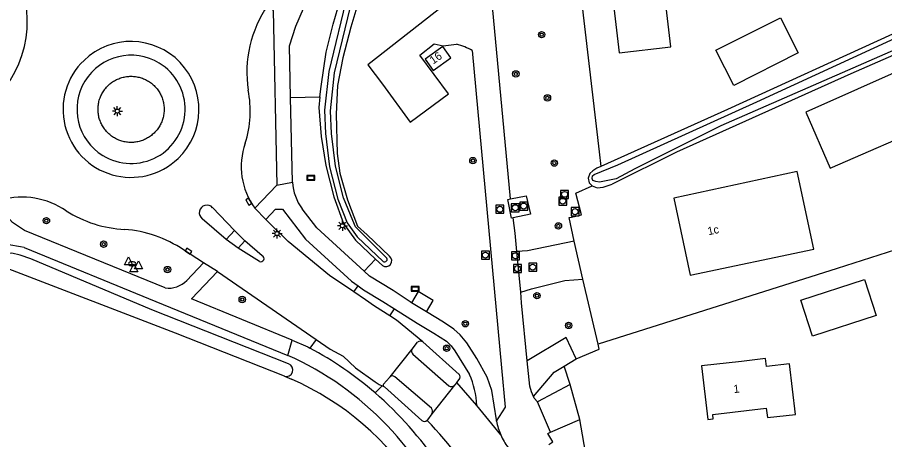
# Model space of a CAD drawing. Extents: x 140000 to 143000, y 403500 to 406000.
# Drawn here: x 140453.4 to 140561.8, y 404433.8 to 404486.5 of the extents above; entities that cross this region are included whole.
import ezdxf

# ---------------------------------------------------------------- set-up
doc = ezdxf.new("R2010")
doc.units = 0
for name, color, linetype in [('gg-afsc-hekwerk', 7, 'Continuous'), ('gg-anno-huisnummerreeks BGT', 7, 'Continuous'), ('gg-bbg-bijgebouw', 7, 'Continuous'), ('gg-bbg-gedigitaliseerde bijgebouw', 7, 'Continuous'), ('gg-bbg-hoofdgebouw', 7, 'Continuous'), ('gg-knt-verharding', 7, 'Continuous'), ('gg-knt-verharding nz', 7, 'Continuous'), ('gg-kntw-bovenkant insteek waterloop', 7, 'Continuous'), ('gg-kntw-waterlijn', 7, 'Continuous'), ('gg-kwrk-betonelement', 7, 'Continuous'), ('gt-grn-groengrens', 7, 'Continuous'), ('gt-grn-groengrens NZ', 7, 'Continuous'), ('gt-grn-vlakafsluiter', 7, 'Continuous'), ('gt-grn-weggrens', 7, 'Continuous'), ('gt-symb-boom', 7, 'Continuous'), ('gt-symb-brandkraan', 7, 'Continuous'), ('gt-symb-informatiebord', 7, 'Continuous'), ('gt-symb-kolk', 7, 'Continuous'), ('gt-symb-lichtmast', 7, 'Continuous'), ('gt-symb-reclamebord', 7, 'Continuous'), ('gt-symb-rioolschacht', 7, 'Continuous'), ('gt-symb-waterafsluiter', 7, 'Continuous')]:
    doc.layers.add(name, color=color, linetype=linetype)

# ---------------------------------------------------------------- blocks, each defined once
blk = doc.blocks.new('gt0-RS')
at = {"layer": 'gt-symb-rioolschacht'}
blk.add_lwpolyline([(-0.5, -0.5), (0.5, -0.5), (0.5, 0.5), (-0.5, 0.5)], close=True, dxfattribs=at)
blk.add_circle((0, 0), 0.375, dxfattribs=at)
blk = doc.blocks.new('gt0-BOOM')
at = {"layer": 'gt-symb-boom'}
for radius in [0.4, 0.2]:
    blk.add_circle((0, 0), radius, dxfattribs=at)
blk = doc.blocks.new('gt0-IBORD')
at = {"layer": 'gt-symb-informatiebord'}
blk.add_lwpolyline([(-0.5, 0.29), (-0.5, -0.29), (0.5, -0.29), (0.5, 0.29), (-0.5, 0.29)], dxfattribs=at)
blk.add_lwpolyline([(-0.42, -0.21), (0.42, -0.21), (0.42, 0.21), (-0.42, 0.21)], close=True, dxfattribs=at)
blk = doc.blocks.new('gt0-LMAST')
at = {"layer": 'gt-symb-lichtmast'}
for p, q in [((-0.18, 0.17), (-0.45, 0.44)), ((-0.01, 0.25), (-0.01, 0.62)), ((0.17, 0.17), (0.44, 0.44)), ((-0.26, 0), (-0.63, 0)), ((-0.18, -0.18), (-0.45, -0.45)), ((-0.01, -0.25), (-0.01, -0.63)), ((0.44, -0.45), (0.17, -0.18)), ((0.24, 0), (0.62, 0))]:
    blk.add_line(p, q, dxfattribs=at)
blk.add_circle((-0.01, 0), 0.25, dxfattribs=at)
blk = doc.blocks.new('gt0-RBORD')
at = {"layer": 'gt-symb-reclamebord'}
blk.add_lwpolyline([(-0.5, 0.29), (-0.5, -0.29), (0.5, -0.29), (0.5, 0.29), (-0.5, 0.29)], dxfattribs=at)
blk.add_lwpolyline([(-0.42, -0.21), (0.42, -0.21), (0.42, 0.21), (-0.42, 0.21)], close=True, dxfattribs=at)
blk = doc.blocks.new('gt0-KOLK')
at = {"layer": 'gt-symb-kolk'}
blk.add_lwpolyline([(0, 0), (0.38, 0), (0.38, 0.4), (-0.37, 0.4), (-0.37, 0), (0, 0)], dxfattribs=at)
blk = doc.blocks.new('gt0-WAFSL')
at = {"layer": 'gt-symb-waterafsluiter'}
for p, q in [((-0.5, -0.33), (0, 0.67)), ((0, 0.67), (0.5, -0.33)), ((0.5, -0.33), (-0.5, -0.33))]:
    blk.add_line(p, q, dxfattribs=at)
blk = doc.blocks.new('gt0-BR')
at = {"layer": 'gt-symb-brandkraan'}
for centre, radius, start, end in [((-0.24, 0), 0.206, 107.5669, 252.4331), ((0.6, -2.66), 3, 106.892, 107.5669), ((0, -0.69), 0.938, 73.108, 106.892), ((-0.6, -2.66), 3, 72.4331, 73.108), ((0.24, 0), 0.206, 287.567, 72.4331), ((0.6, 2.66), 3, 252.4331, 253.108), ((0, 0.69), 0.938, 253.108, 286.8921), ((-0.6, 2.66), 3, 286.8921, 287.567)]:
    blk.add_arc(centre, radius, start, end, dxfattribs=at)

msp = doc.modelspace()

# ---------------------------------------------------------------- linework, layer by layer
at = {"layer": 'gg-afsc-hekwerk'}
msp.add_lwpolyline([(140522.62, 404461.55), (140523.86, 404461.84), (140523.16, 404464.53), (140525.23, 404465.47)], dxfattribs=at)
at = {"layer": 'gg-bbg-bijgebouw'}
for points in [[(140528.58, 404482.06), (140535.03, 404482.81), (140533.59, 404495.22), (140527.14, 404494.47), (140528.58, 404482.06)], [(140564.83, 404480.4), (140551.92, 404474.66), (140554.95, 404467.67), (140567.98, 404473.32), (140564.83, 404480.4)], [(140560.68, 404449.24), (140552.74, 404446.68), (140551.29, 404451.18), (140559.22, 404453.75), (140560.68, 404449.24)]]:
    msp.add_lwpolyline(points, dxfattribs=at)
at = {"layer": 'gg-bbg-gedigitaliseerde bijgebouw'}
msp.add_lwpolyline([(140540.68, 404482.42), (140548.72, 404486.46), (140550.94, 404482.05), (140542.9, 404478.01), (140540.68, 404482.42)], dxfattribs=at)
at = {"layer": 'gg-bbg-hoofdgebouw'}
for points in [[(140507.57, 404481.43), (140506.57, 404482.86), (140504.33, 404481.28), (140505.33, 404479.86), (140507.57, 404481.43)], [(140550.82, 404467.25), (140535.42, 404463.91), (140537.46, 404454.28), (140552.91, 404457.56), (140550.82, 404467.25)], [(140546.99, 404442.89), (140546.87, 404443.87), (140543.85, 404443.51), (140538.88, 404442.99), (140539.66, 404436.28), (140540.33, 404436.35), (140540.27, 404436.89), (140546.97, 404437.7), (140547.11, 404436.5), (140550.63, 404436.91), (140549.88, 404443.23), (140546.99, 404442.89)]]:
    msp.add_lwpolyline(points, dxfattribs=at)
at = {"layer": 'gg-knt-verharding'}
for p, q in [((140487.75, 404465.9), (140487.53, 404476.49)), ((140485.81, 404465.55), (140483.06, 404462.66)), ((140477.79, 404462.73), (140480.53, 404459.89)), ((140484.43, 404461.26), (140483.06, 404462.66)), ((140479.49, 404458.75), (140476.48, 404461.34)), ((140479.49, 404458.75), (140480.53, 404459.89)), ((140480.53, 404459.89), (140481.81, 404458.57)), ((140480.99, 404457.69), (140479.49, 404458.75)), ((140480.99, 404457.69), (140481.81, 404458.57)), ((140483.99, 404456.72), (140481.81, 404458.57)), ((140476.66, 404455.85), (140474.13, 404457.47)), ((140483.64, 404456), (140480.99, 404457.69)), ((140476.66, 404455.85), (140474.57, 404453.64)), ((140478.39, 404454.76), (140476.66, 404455.85)), ((140478.39, 404454.76), (140490.71, 404446.27)), ((140504.5, 404449.73), (140502.65, 404450.86)), ((140502.73, 404445.04), (140503.38, 404445.93)), ((140502.82, 404444.45), (140507.31, 404440.47)), ((140521.73, 404442.95), (140523.23, 404443.83)), ((140505.12, 404437.7), (140500.54, 404441.58)), ((140508.3, 404440.9), (140508, 404440.54)), ((140510.81, 404438.03), (140508.3, 404440.9)), ((140522.45, 404440.65), (140518.39, 404438.46)), ((140498.98, 404440.47), (140499.19, 404440.38)), ((140513.8, 404434.35), (140510.81, 404438.03)), ((140520.01, 404434.7), (140523.65, 404436.26))]:
    msp.add_line(p, q, dxfattribs=at)
for points in [[(140520.96, 404513.15), (140521.2, 404511.38), (140526.1, 404469.69), (140526.29, 404467.87)], [(140487.53, 404476.49), (140487.39, 404482.93), (140488.2, 404485.4), (140489.14, 404487.62), (140490.18, 404489.76), (140497.41, 404498.62)], [(140515.01, 404463.83), (140512.75, 404487.86), (140513.62, 404490.15), (140513.59, 404491.55), (140512.68, 404492.73), (140497.19, 404480.57), (140499.03, 404478.17), (140502.45, 404473.42), (140507.27, 404476.95), (140503.69, 404481.79), (140505.47, 404483.18), (140506.59, 404482.94), (140508.27, 404483.14)], [(140484.67, 404488), (140485.35, 404487.37), (140485.81, 404465.55)], [(140513.27, 404436.07), (140514.4, 404437.81), (140513.94, 404442.74), (140510.24, 404482.36)], [(140471.84, 404452.7), (140454.28, 404459.86), (140452.8, 404460.86), (140452.12, 404461.61), (140451.39, 404463.71)], [(140484.43, 404461.26), (140485.66, 404462.56), (140486.51, 404462.55), (140489.41, 404458.81), (140495.13, 404453.55), (140495.96, 404452.95)], [(140496.72, 404454.79), (140490.81, 404460.19), (140488.97, 404462.59)], [(140495.44, 404452.2), (140492.38, 404454.24), (140487.22, 404458.49), (140484.43, 404461.26)], [(140515.81, 404457.25), (140515.6, 404459.53), (140515.32, 404461.45)], [(140575.92, 404441.74), (140571.45, 404460.14), (140555.84, 404455.11), (140525.94, 404445.69)], [(140522.95, 404458.56), (140517.14, 404457.34), (140515.81, 404457.25)], [(140454.25, 404457.76), (140470.71, 404451.02), (140487.17, 404444.27)], [(140487.71, 404446.19), (140475.16, 404451.36), (140478.39, 404454.76)], [(140502.65, 404450.86), (140502.48, 404450.97), (140500.34, 404452.38), (140497.38, 404454.18), (140496.72, 404454.79)], [(140516.28, 404452.17), (140517.61, 404452.61), (140521.79, 404453.64), (140524.06, 404453.81)], [(140495.96, 404452.95), (140496.63, 404452.47), (140499.05, 404451.01), (140500.5, 404450.1)], [(140499.92, 404449.22), (140498.03, 404450.43), (140496.9, 404451.22), (140495.44, 404452.2)], [(140517.1, 404443.58), (140516.36, 404450.85), (140516.28, 404452.17)], [(140500.5, 404450.1), (140503.36, 404448.32), (140505.44, 404447.07), (140507, 404446.05), (140507.6, 404445.49), (140508.06, 404444.84), (140509.9, 404441.9)], [(140513.27, 404436.07), (140513.24, 404436.22), (140512.66, 404439.89), (140512.1, 404441.57), (140510.81, 404443.9), (140509.53, 404445.84), (140508.72, 404446.86), (140507.92, 404447.54), (140506.62, 404448.44), (140504.5, 404449.73)], [(140504.05, 404445.95), (140500.76, 404448.68), (140499.92, 404449.22)], [(140487.71, 404446.19), (140489.67, 404445.33), (140489.94, 404445.18)], [(140490.71, 404446.27), (140492.47, 404445.06), (140494.08, 404444.18), (140495.62, 404442.74), (140498.08, 404440.99), (140498.6, 404440.64), (140498.98, 404440.47)], [(140523.23, 404443.83), (140521.97, 404446.53), (140517.1, 404443.58)], [(140517.87, 404439.14), (140520.48, 404442.18), (140521.73, 404442.95)], [(140499.15, 404440.69), (140499.89, 404441.51), (140499.96, 404441.59)], [(140518.39, 404438.46), (140517.97, 404438.95), (140517.87, 404439.14)], [(140505.17, 404436.99), (140504.62, 404436.21), (140504.58, 404436.17)], [(140519.81, 404433.16), (140520.28, 404433.47), (140519.66, 404434.54), (140520.01, 404434.7)]]:
    msp.add_lwpolyline(points, dxfattribs=at)
for centre, radius, start, end in [((140441.02, 404485.97), 13.61, 298.4785, 15.9057), ((140496.9, 404479.62), 14.83, 145.5807, 188.5723), ((140467.59, 404475), 8.49, 313.788, 133.7499), ((140506.5, 404475.84), 7.51, 60.1621, 76.3458), ((140467.59, 404475), 8.49, 133.7499, 313.788), ((140469.08, 404474.8), 13.41, 342.5234, 11.2135), ((140490.07, 404467.83), 8.71, 160.2347, 216.4345), ((140494.14, 404466.38), 6.41, 184.345, 216.2764), ((140453.95, 404454.25), 9.8, 55.5742, 105.1133), ((140467.59, 404475.16), 15.17, 237.724, 267.0571), ((140477.08, 404462.09), 0.957, 41.869, 231.7851), ((140465.68, 404444.92), 15.13, 56.0472, 85.7271), ((140450.4, 404440.5), 17.68, 77.4258, 102.5145), ((140483.81, 404456.37), 0.401, 245.3953, 63.2659), ((140472.26, 404455.91), 3.24, 262.5951, 315.4691), ((140503.73, 404445.47), 0.576, 56.5546, 127.7192), ((140468.75, 404405.6), 44.9, 49.192, 61.8333), ((140503.06, 404444.79), 0.42, 142.7754, 234.239), ((140471.33, 404408.63), 39.01, 21.2344, 66.0399), ((140500.24, 404441.3), 0.409, 42.8173, 134.0493), ((140498.71, 404437.24), 12.12, 3.748, 22.6407), ((140499.32, 404440.55), 0.22, 143.2526, 234.6549), ((140468.74, 404405.61), 44.9, 18.6655, 49.1813), ((140507.61, 404440.95), 0.57, 238.8281, 313.4677), ((140504.72, 404437.31), 0.554, 324.5656, 44.0208), ((140472.26, 404404.56), 45.2, 12.7234, 44.3624), ((140520.95, 404437.49), 7.82, 190.4271, 203.6944)]:
    msp.add_arc(centre, radius, start, end, dxfattribs=at)
at = {"layer": 'gg-knt-verharding nz'}
for p, q in [((140516.28, 404452.17), (140515.81, 404457.25)), ((140520.01, 404434.7), (140518.39, 404438.46))]:
    msp.add_line(p, q, dxfattribs=at)
msp.add_lwpolyline([(140517.87, 404439.14), (140517.61, 404439.72), (140517.43, 404440.44), (140517.1, 404443.58)], dxfattribs=at)
at = {"layer": 'gg-kntw-bovenkant insteek waterloop'}
msp.add_line((140498.14, 404456.31), (140499.01, 404455.5), dxfattribs=at)
for points in [[(140666.62, 404527.97), (140659.46, 404524.87), (140640.73, 404516.48), (140623.81, 404509.02), (140621.4, 404508.04), (140620.12, 404507.42), (140618.62, 404506.41), (140617.55, 404505.74), (140597.26, 404497.06), (140576.48, 404487.74), (140557.53, 404479.45), (140535.75, 404469.66), (140527.71, 404465.66)], [(140491.19, 404476.56), (140491.33, 404477.87), (140491.97, 404482.14), (140492.87, 404485.65), (140493.74, 404488.71), (140494.69, 404491.34), (140495.81, 404493.54), (140497.39, 404496.11), (140499.15, 404498.51), (140502.16, 404502.15), (140505.71, 404505.21), (140507.48, 404506.7), (140517.05, 404513.8)], [(140621.8, 404510.82), (140612.07, 404506.52), (140586.99, 404495.35), (140562.75, 404484.41), (140542.11, 404474.98), (140526.29, 404467.87)], [(140505.76, 404502.31), (140503.67, 404500.63), (140501.67, 404498.34), (140499.95, 404496.3), (140497.92, 404492.66), (140496.32, 404489.47), (140495.05, 404485.29), (140494.07, 404481.44), (140493.38, 404478.01), (140493.21, 404474.4), (140493.35, 404469.5), (140493.7, 404467.04), (140494.65, 404463.69), (140495.88, 404460.41), (140497.11, 404459.33), (140499.87, 404456.67)], [(140491.19, 404476.56), (140491.05, 404475.26), (140491.35, 404471.61), (140491.94, 404467.99), (140492.92, 404464.08), (140494.16, 404460.77), (140495.62, 404458.67), (140498.14, 404456.31)], [(140526.29, 404467.87), (140525.8, 404467.65), (140525.31, 404467.35), (140524.9, 404466.99), (140524.73, 404466.43), (140524.84, 404465.83), (140525.23, 404465.47)], [(140525.23, 404465.47), (140525.42, 404465.39), (140525.83, 404465.22), (140526.57, 404465.3), (140527.71, 404465.66)], [(140487.27, 404443.22), (140470.2, 404449.98), (140455.09, 404456.32), (140453.74, 404456.81), (140452.71, 404457.05), (140452.26, 404456.99), (140451.76, 404456.55), (140451.57, 404456.09), (140451.56, 404455.67), (140451.82, 404455.3)], [(140486.75, 404441.67), (140473.13, 404447.04), (140452.26, 404455.08), (140451.82, 404455.3)]]:
    msp.add_lwpolyline(points, dxfattribs=at)
for centre, radius, start, end in [((140499.44, 404456.08), 0.728, 233.5478, 53.1062), ((140487, 404442.45), 0.819, 252.4404, 70.0698)]:
    msp.add_arc(centre, radius, start, end, dxfattribs=at)
at = {"layer": 'gg-kntw-waterlijn'}
for points in [[(140517.64, 404513.01), (140510.45, 404507.83), (140502.62, 404501.65), (140498.04, 404496.02), (140494.67, 404489.59), (140492.3, 404479.73), (140491.77, 404474.9), (140491.91, 404471.98), (140492.41, 404467.84), (140493.42, 404463.79), (140494.61, 404460.85), (140495.86, 404459.09), (140499.08, 404456.01)], [(140499.47, 404456.52), (140495.65, 404460.34), (140495.31, 404461.14), (140494.15, 404463.97), (140493.15, 404467.93), (140492.66, 404472.01), (140492.52, 404474.82), (140493.03, 404479.56), (140495.33, 404489.24), (140498.62, 404495.55), (140503.15, 404501.11), (140510.89, 404507.22), (140518.09, 404512.41)], [(140577.84, 404488.98), (140557.79, 404480.15), (140541.28, 404472.97), (140530.56, 404467.57), (140528.22, 404466.34), (140526.13, 404465.91), (140525.68, 404465.98), (140525.31, 404466.11), (140525.2, 404466.39), (140525.27, 404466.69), (140525.47, 404466.87), (140528.4, 404468.09), (140545.77, 404475.93), (140567.76, 404486.05), (140593.6, 404497.59)]]:
    msp.add_lwpolyline(points, dxfattribs=at)
msp.add_arc((140499.27, 404456.27), 0.317, 232.574, 52.1676, dxfattribs=at)
at = {"layer": 'gg-kwrk-betonelement'}
for points in [[(140515.32, 404461.45), (140515.14, 404461.42), (140514.67, 404463.77), (140515.01, 404463.83)], [(140515.01, 404463.83), (140516.97, 404464.22), (140517.49, 404461.92), (140515.32, 404461.45)]]:
    msp.add_lwpolyline(points, dxfattribs=at)
at = {"layer": 'gt-grn-groengrens'}
for p, q in [((140496.72, 404454.79), (140498.14, 404456.31)), ((140525.94, 404445.69), (140524.06, 404453.81)), ((140526.08, 404445.07), (140525.94, 404445.69)), ((140522.45, 404440.65), (140521.73, 404442.95)), ((140486.75, 404441.67), (140487.63, 404441.32)), ((140526.37, 404421.2), (140523.65, 404436.26))]:
    msp.add_line(p, q, dxfattribs=at)
for points in [[(140465.66, 404471.37), (140465.53, 404471.44), (140465.41, 404471.51), (140465.29, 404471.59), (140465.17, 404471.67), (140465.06, 404471.76), (140464.94, 404471.85), (140464.84, 404471.94), (140464.73, 404472.04), (140464.63, 404472.14), (140464.53, 404472.25), (140464.43, 404472.36), (140464.34, 404472.47), (140464.26, 404472.59), (140464.18, 404472.7), (140464.1, 404472.82), (140464.02, 404472.95), (140463.95, 404473.07), (140463.89, 404473.2), (140463.83, 404473.33), (140463.77, 404473.47), (140463.72, 404473.6), (140463.67, 404473.74), (140463.63, 404473.87), (140463.59, 404474.01), (140463.56, 404474.15), (140463.53, 404474.3), (140463.51, 404474.44), (140463.49, 404474.58), (140463.48, 404474.73), (140463.47, 404474.87), (140463.47, 404475.01), (140463.47, 404475.16), (140463.48, 404475.3), (140463.49, 404475.45), (140463.51, 404475.59), (140463.53, 404475.73), (140463.56, 404475.87), (140463.59, 404476.01), (140463.63, 404476.15), (140463.67, 404476.29), (140463.72, 404476.43), (140463.77, 404476.56), (140463.83, 404476.69), (140463.89, 404476.82), (140463.95, 404476.95), (140464.02, 404477.08), (140464.1, 404477.2), (140464.18, 404477.32), (140464.26, 404477.44), (140464.34, 404477.56), (140464.43, 404477.67), (140464.53, 404477.78), (140464.63, 404477.88), (140464.73, 404477.98), (140464.84, 404478.08), (140464.94, 404478.18), (140465.06, 404478.27), (140465.17, 404478.36), (140465.29, 404478.44), (140465.41, 404478.52), (140465.53, 404478.59), (140465.66, 404478.66), (140465.79, 404478.73), (140465.92, 404478.79), (140466.05, 404478.84), (140466.19, 404478.89), (140466.32, 404478.94), (140466.46, 404478.98), (140466.6, 404479.02), (140466.74, 404479.05), (140466.88, 404479.08), (140467.02, 404479.1), (140467.17, 404479.12), (140467.31, 404479.13), (140467.46, 404479.14), (140467.6, 404479.14), (140467.74, 404479.14), (140467.89, 404479.13), (140468.03, 404479.12), (140468.17, 404479.1), (140468.32, 404479.08), (140468.46, 404479.05), (140468.6, 404479.02), (140468.74, 404478.98), (140468.88, 404478.94), (140469.01, 404478.89), (140469.15, 404478.84), (140469.28, 404478.79), (140469.41, 404478.73), (140469.54, 404478.66), (140469.66, 404478.59), (140469.79, 404478.52), (140469.91, 404478.44), (140470.03, 404478.36), (140470.14, 404478.27), (140470.25, 404478.18), (140470.36, 404478.08), (140470.47, 404477.98), (140470.57, 404477.88), (140470.67, 404477.78), (140470.76, 404477.67), (140470.85, 404477.56), (140470.94, 404477.44), (140471.02, 404477.32), (140471.1, 404477.2), (140471.18, 404477.08), (140471.25, 404476.95), (140471.31, 404476.82), (140471.37, 404476.69), (140471.43, 404476.56), (140471.48, 404476.43), (140471.53, 404476.29), (140471.57, 404476.15), (140471.61, 404476.01), (140471.64, 404475.87), (140471.67, 404475.73), (140471.69, 404475.59), (140471.71, 404475.45), (140471.72, 404475.3), (140471.73, 404475.16), (140471.73, 404475.01), (140471.73, 404474.87), (140471.72, 404474.73), (140471.71, 404474.58), (140471.69, 404474.44), (140471.67, 404474.3), (140471.64, 404474.15), (140471.61, 404474.01), (140471.57, 404473.87), (140471.53, 404473.74), (140471.48, 404473.6), (140471.43, 404473.47), (140471.37, 404473.33), (140471.31, 404473.2), (140471.25, 404473.07), (140471.18, 404472.95), (140471.1, 404472.82), (140471.02, 404472.7), (140470.94, 404472.59), (140470.85, 404472.47), (140470.76, 404472.36), (140470.67, 404472.25), (140470.57, 404472.14), (140470.47, 404472.04), (140470.36, 404471.94), (140470.25, 404471.85), (140470.14, 404471.76), (140470.03, 404471.67), (140469.91, 404471.59), (140469.79, 404471.51), (140469.66, 404471.44), (140469.54, 404471.37), (140469.41, 404471.3), (140469.28, 404471.24), (140469.15, 404471.18), (140469.01, 404471.13), (140468.88, 404471.09), (140468.74, 404471.04), (140468.6, 404471.01), (140468.46, 404470.97), (140468.32, 404470.95), (140468.17, 404470.92), (140468.03, 404470.91), (140467.89, 404470.89), (140467.74, 404470.89), (140467.6, 404470.88), (140467.46, 404470.89), (140467.31, 404470.89), (140467.17, 404470.91), (140467.02, 404470.92), (140466.88, 404470.95), (140466.74, 404470.97), (140466.6, 404471.01), (140466.46, 404471.04), (140466.32, 404471.09), (140466.19, 404471.13), (140466.05, 404471.18), (140465.92, 404471.24), (140465.79, 404471.3), (140465.66, 404471.37)], [(140522.95, 404458.56), (140522.34, 404461.51), (140522.62, 404461.55)], [(140504.5, 404449.73), (140505.34, 404451.14), (140503.47, 404452.24), (140502.65, 404450.86)]]:
    msp.add_lwpolyline(points, dxfattribs=at)
msp.add_arc((140473.38, 404408.77), 35.53, 32.1454, 66.354, dxfattribs=at)
at = {"layer": 'gt-grn-groengrens NZ'}
for p, q in [((140504.05, 404445.95), (140508.59, 404441.91)), ((140508.3, 404440.9), (140508.61, 404441.25))]:
    msp.add_line(p, q, dxfattribs=at)
msp.add_lwpolyline([(140499.19, 404440.38), (140499.27, 404440.34), (140503.94, 404436.14)], dxfattribs=at)
for centre, radius, start, end in [((140467.6, 404475.01), 6.76, 58.5726, 238.5349), ((140467.6, 404475.01), 6.76, 238.5421, 58.5654), ((140508.18, 404441.57), 0.533, 323.0173, 39.756), ((140504.24, 404436.5), 0.472, 230.5272, 315.2426)]:
    msp.add_arc(centre, radius, start, end, dxfattribs=at)
at = {"layer": 'gt-grn-vlakafsluiter'}
for p, q in [((140524.06, 404453.81), (140522.95, 404458.56)), ((140523.23, 404443.83), (140526.08, 404445.07)), ((140523.65, 404436.26), (140522.45, 404440.65))]:
    msp.add_line(p, q, dxfattribs=at)
at = {"layer": 'gt-grn-weggrens'}
for p, q in [((140487.53, 404476.49), (140491.19, 404476.56)), ((140485.81, 404465.55), (140487.75, 404465.9)), ((140495.44, 404452.2), (140495.96, 404452.95)), ((140499.92, 404449.22), (140500.5, 404450.1)), ((140487.17, 404444.27), (140487.71, 404446.19)), ((140490.71, 404446.27), (140489.94, 404445.18)), ((140499.96, 404441.59), (140502.73, 404445.04)), ((140498.98, 404440.47), (140498.09, 404439.59)), ((140508, 404440.54), (140505.17, 404436.99))]:
    msp.add_line(p, q, dxfattribs=at)
msp.add_arc((140520.96, 404437.49), 7.83, 203.6816, 216.9045, dxfattribs=at)

# ---------------------------------------------------------------- block references
at = {"layer": 'gt-symb-boom'}
for p in [(140518.9, 404484.34), (140515.67, 404479.44), (140519.62, 404476.44), (140510.31, 404468.61), (140520.48, 404468.3), (140457.02, 404461.11), (140520.99, 404460.45), (140464.17, 404458.17), (140472.15, 404455), (140481.49, 404451.26), (140518.31, 404451.74), (140509.36, 404448.23), (140522.27, 404448.02), (140507.03, 404445.17)]:
    msp.add_blockref('gt0-BOOM', p, dxfattribs=at)
at = {"layer": 'gt-symb-brandkraan'}
msp.add_blockref('gt0-BR', (140467.73, 404455.72), dxfattribs=at)
at = {"layer": 'gt-symb-informatiebord'}
msp.add_blockref('gt0-IBORD', (140503.1, 404452.6), dxfattribs=at)
at = {"layer": 'gt-symb-kolk'}
for p, rotation in [((140482.47, 404463.57), 119.06322601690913), ((140474.67, 404457.13), -32.671712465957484)]:
    msp.add_blockref('gt0-KOLK', p, dxfattribs=dict(at, rotation=rotation))
at = {"layer": 'gt-symb-lichtmast'}
for p in [(140465.89, 404474.79), (140494.01, 404460.47), (140485.84, 404459.49)]:
    msp.add_blockref('gt0-LMAST', p, dxfattribs=at)
at = {"layer": 'gt-symb-reclamebord'}
msp.add_blockref('gt0-RBORD', (140490.06, 404466.47), dxfattribs=at)
at = {"layer": 'gt-symb-rioolschacht'}
for p in [(140521.77, 404464.38), (140516.66, 404462.93), (140521.53, 404463.55), (140513.68, 404462.53), (140515.6, 404462.72), (140523.08, 404462.23), (140511.87, 404456.8), (140515.62, 404456.72), (140517.78, 404455.3), (140515.88, 404455.12)]:
    msp.add_blockref('gt0-RS', p, dxfattribs=at)
at = {"layer": 'gt-symb-waterafsluiter'}
for p in [(140467.29, 404455.9), (140468.52, 404455.4), (140467.96, 404455.03)]:
    msp.add_blockref('gt0-WAFSL', p, dxfattribs=at)

# ---------------------------------------------------------------- texts
at = {"layer": 'gg-anno-huisnummerreeks BGT'}
for s, rotation, p in [('16', 35.1, (140505.34, 404480.6)), ('1c', 12, (140539.74, 404459.28)), ('1', 6.6, (140542.92, 404439.56))]:
    msp.add_text(s, height=1, rotation=rotation, dxfattribs=at).set_placement(p)

doc.saveas('drawing.dxf')
